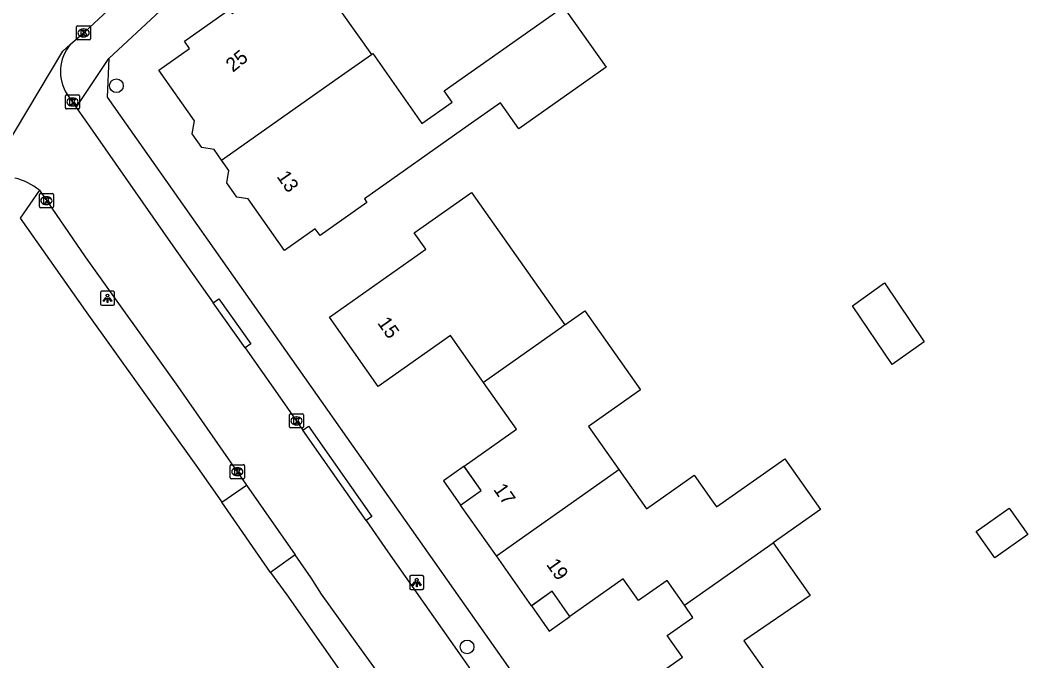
# Model space of a CAD drawing. Extents: x 161772 to 163123, y 383092 to 383917.
# Drawn here: x 162495.4 to 162567, y 383703.8 to 383749.3 of the extents above; entities that cross this region are included whole.
import ezdxf

# ---------------------------------------------------------------- set-up
doc = ezdxf.new("R2010")
doc.units = 0
for name, color, linetype in [('IMGEO_Boom', 7, 'Continuous'), ('IMGEO_Kolk', 7, 'Continuous'), ('IMGEO_Lichtpunt', 7, 'Continuous'), ('IMGEO_Pand', 7, 'Continuous'), ('IMGEO_Pand_nummerreeks', 7, 'Continuous'), ('IMGEO_Pand_overbouw', 7, 'Continuous'), ('IMGEO_Rijbaan_lokaal_open', 7, 'Continuous'), ('IMGEO_Voetpad_open', 7, 'Continuous')]:
    doc.layers.add(name, color=color, linetype=linetype)

msp = doc.modelspace()

# ---------------------------------------------------------------- linework, layer by layer
at = {"layer": 'IMGEO_Boom'}
for centre in [(162502.224, 383744.673), (162527.147, 383704.793)]:
    msp.add_circle(centre, 0.489, dxfattribs=at)
at = {"layer": 'IMGEO_Kolk'}
for p, q in [((162499.386, 383748.003), (162499.386, 383748.855)), ((162499.461, 383748.929), (162500.313, 383748.929)), ((162499.874, 383748.709), (162499.899, 383748.709)), ((162500.387, 383748.855), (162500.387, 383748.003)), ((162500.313, 383747.929), (162499.461, 383747.929)), ((162499.897, 383748.149), (162499.872, 383748.149)), ((162498.597, 383743.095), (162498.597, 383743.947)), ((162498.672, 383744.021), (162499.524, 383744.021)), ((162499.085, 383743.801), (162499.11, 383743.801)), ((162499.598, 383743.947), (162499.598, 383743.095)), ((162499.524, 383743.021), (162498.672, 383743.021)), ((162499.108, 383743.241), (162499.083, 383743.241)), ((162496.819, 383737.006), (162497.671, 383737.006)), ((162496.744, 383736.08), (162496.744, 383736.932)), ((162497.232, 383736.786), (162497.257, 383736.786)), ((162497.745, 383736.932), (162497.745, 383736.08)), ((162497.671, 383736.006), (162496.819, 383736.006)), ((162497.255, 383736.226), (162497.23, 383736.226)), ((162514.522, 383720.427), (162514.522, 383721.279)), ((162514.597, 383721.353), (162515.449, 383721.353)), ((162515.523, 383721.279), (162515.523, 383720.427)), ((162515.033, 383720.573), (162515.008, 383720.573)), ((162515.01, 383721.133), (162515.035, 383721.133)), ((162515.449, 383720.353), (162514.597, 383720.353)), ((162510.315, 383716.818), (162510.315, 383717.67)), ((162510.39, 383717.744), (162511.242, 383717.744)), ((162511.316, 383717.67), (162511.316, 383716.818)), ((162510.826, 383716.964), (162510.801, 383716.964)), ((162510.803, 383717.524), (162510.828, 383717.524)), ((162511.242, 383716.744), (162510.39, 383716.744))]:
    msp.add_line(p, q, dxfattribs=at)
for points in [[(162499.386, 383748.003), (162499.386, 383748.855)], [(162499.461, 383748.929), (162500.313, 383748.929)], [(162499.707, 383748.629), (162499.83, 383748.629), (162499.83, 383748.478), (162499.96, 383748.629), (162500.124, 383748.629), (162499.978, 383748.478), (162500.131, 383748.229), (162499.979, 383748.229), (162499.894, 383748.393), (162499.83, 383748.326), (162499.83, 383748.229), (162499.707, 383748.229), (162499.707, 383748.629)], [(162500.387, 383748.855), (162500.387, 383748.003)], [(162500.313, 383747.929), (162499.461, 383747.929)], [(162498.597, 383743.095), (162498.597, 383743.947)], [(162498.672, 383744.021), (162499.524, 383744.021)], [(162498.918, 383743.721), (162499.041, 383743.721), (162499.041, 383743.57), (162499.171, 383743.721), (162499.335, 383743.721), (162499.189, 383743.57), (162499.342, 383743.321), (162499.19, 383743.321), (162499.105, 383743.485), (162499.041, 383743.418), (162499.041, 383743.321), (162498.918, 383743.321), (162498.918, 383743.721)], [(162499.598, 383743.947), (162499.598, 383743.095)], [(162499.524, 383743.021), (162498.672, 383743.021)], [(162496.819, 383737.006), (162497.671, 383737.006)], [(162496.744, 383736.08), (162496.744, 383736.932)], [(162497.065, 383736.706), (162497.188, 383736.706), (162497.188, 383736.555), (162497.318, 383736.706), (162497.482, 383736.706), (162497.336, 383736.555), (162497.489, 383736.306), (162497.337, 383736.306), (162497.252, 383736.47), (162497.188, 383736.403), (162497.188, 383736.306), (162497.065, 383736.306), (162497.065, 383736.706)], [(162497.745, 383736.932), (162497.745, 383736.08)], [(162497.671, 383736.006), (162496.819, 383736.006)], [(162514.522, 383720.427), (162514.522, 383721.279)], [(162514.597, 383721.353), (162515.449, 383721.353)], [(162515.523, 383721.279), (162515.523, 383720.427)], [(162514.843, 383721.053), (162514.966, 383721.053), (162514.966, 383720.902), (162515.096, 383721.053), (162515.26, 383721.053), (162515.114, 383720.902), (162515.267, 383720.653), (162515.115, 383720.653), (162515.03, 383720.817), (162514.966, 383720.75), (162514.966, 383720.653), (162514.843, 383720.653), (162514.843, 383721.053)], [(162515.449, 383720.353), (162514.597, 383720.353)], [(162510.315, 383716.818), (162510.315, 383717.67)], [(162510.39, 383717.744), (162511.242, 383717.744)], [(162511.316, 383717.67), (162511.316, 383716.818)], [(162510.636, 383717.444), (162510.759, 383717.444), (162510.759, 383717.293), (162510.889, 383717.444), (162511.053, 383717.444), (162510.907, 383717.293), (162511.06, 383717.044), (162510.908, 383717.044), (162510.823, 383717.208), (162510.759, 383717.141), (162510.759, 383717.044), (162510.636, 383717.044), (162510.636, 383717.444)], [(162511.242, 383716.744), (162510.39, 383716.744)]]:
    msp.add_lwpolyline(points, dxfattribs=at)
for centre, start, end in [((162499.463, 383748.853), 91.55205, 178.44795), ((162499.463, 383748.853), 91.55205, 178.44795), ((162500.311, 383748.853), 1.55205, 88.44795), ((162500.311, 383748.853), 1.55205, 88.44795), ((162499.463, 383748.005), 181.55205, 268.44795), ((162499.463, 383748.005), 181.55205, 268.44795), ((162500.311, 383748.005), 271.55205, 358.44795), ((162500.311, 383748.005), 271.55205, 358.44795), ((162498.674, 383743.945), 91.55205, 178.44795), ((162498.674, 383743.945), 91.55205, 178.44795), ((162499.522, 383743.945), 1.55205, 88.44795), ((162499.522, 383743.945), 1.55205, 88.44795), ((162498.674, 383743.097), 181.55205, 268.44795), ((162498.674, 383743.097), 181.55205, 268.44795), ((162499.522, 383743.097), 271.55205, 358.44795), ((162499.522, 383743.097), 271.55205, 358.44795), ((162496.821, 383736.93), 91.55205, 178.44795), ((162496.821, 383736.93), 91.55205, 178.44795), ((162497.669, 383736.93), 1.55205, 88.44795), ((162497.669, 383736.93), 1.55205, 88.44795), ((162496.821, 383736.082), 181.55205, 268.44795), ((162496.821, 383736.082), 181.55205, 268.44795), ((162497.669, 383736.082), 271.55205, 358.44795), ((162497.669, 383736.082), 271.55205, 358.44795), ((162514.599, 383721.277), 91.55205, 178.44795), ((162514.599, 383721.277), 91.55205, 178.44795), ((162515.447, 383721.277), 1.55205, 88.44795), ((162515.447, 383721.277), 1.55205, 88.44795), ((162514.599, 383720.429), 181.55205, 268.44795), ((162514.599, 383720.429), 181.55205, 268.44795), ((162515.447, 383720.429), 271.55205, 358.44795), ((162515.447, 383720.429), 271.55205, 358.44795), ((162510.392, 383717.668), 91.55205, 178.44795), ((162510.392, 383717.668), 91.55205, 178.44795), ((162511.24, 383717.668), 1.55205, 88.44795), ((162511.24, 383717.668), 1.55205, 88.44795), ((162510.392, 383716.82), 181.55205, 268.44795), ((162510.392, 383716.82), 181.55205, 268.44795), ((162511.24, 383716.82), 271.55205, 358.44795), ((162511.24, 383716.82), 271.55205, 358.44795)]:
    msp.add_arc(centre, 0.0765, start, end, dxfattribs=at)
for centre, major_axis, ratio, start_param, end_param in [((162499.873, 383748.429), (-0.387, 0.002), 0.722429, 4.712389, 7.853982), ((162499.898, 383748.429), (-0.39, 0.002), 0.717154, 1.570796, 4.712389), ((162499.084, 383743.521), (-0.387, 0.002), 0.722429, 4.712389, 7.853982), ((162499.109, 383743.521), (-0.39, 0.002), 0.717154, 1.570796, 4.712389), ((162497.231, 383736.506), (-0.387, 0.002), 0.722429, 4.712389, 7.853982), ((162497.256, 383736.506), (-0.39, 0.002), 0.717154, 1.570796, 4.712389), ((162515.009, 383720.853), (-0.387, 0.002), 0.722429, 4.712389, 7.853982), ((162515.034, 383720.853), (-0.39, 0.002), 0.717154, 1.570796, 4.712389), ((162510.802, 383717.244), (-0.387, 0.002), 0.722429, 4.712389, 7.853982), ((162510.827, 383717.244), (-0.39, 0.002), 0.717154, 1.570796, 4.712389)]:
    msp.add_ellipse(centre, major_axis=major_axis, ratio=ratio, start_param=start_param, end_param=end_param, dxfattribs=at)
at = {"layer": 'IMGEO_Lichtpunt'}
for p, q in [((162501.087, 383729.97), (162501.087, 383729.163)), ((162501.087, 383729.97), (162501.087, 383729.163)), ((162501.989, 383730.065), (162501.181, 383730.065)), ((162501.989, 383730.065), (162501.181, 383730.065)), ((162502.083, 383729.163), (162502.083, 383729.97)), ((162502.083, 383729.163), (162502.083, 383729.97)), ((162501.181, 383729.069), (162501.989, 383729.069)), ((162501.181, 383729.069), (162501.989, 383729.069)), ((162523.067, 383709.77), (162523.067, 383708.963)), ((162523.067, 383709.77), (162523.067, 383708.963)), ((162523.969, 383709.865), (162523.161, 383709.865)), ((162523.969, 383709.865), (162523.161, 383709.865)), ((162524.063, 383708.963), (162524.063, 383709.77)), ((162524.063, 383708.963), (162524.063, 383709.77)), ((162523.161, 383708.869), (162523.969, 383708.869)), ((162523.161, 383708.869), (162523.969, 383708.869))]:
    msp.add_line(p, q, dxfattribs=at)
for points in [[(162501.461, 383729.634), (162501.5, 383729.606), (162501.312, 383729.344), (162501.274, 383729.371), (162501.461, 383729.634)], [(162501.563, 383729.586), (162501.61, 383729.586), (162501.61, 383729.264), (162501.563, 383729.264), (162501.563, 383729.586)], [(162501.673, 383729.606), (162501.711, 383729.633), (162501.898, 383729.371), (162501.859, 383729.343), (162501.673, 383729.606)], [(162523.441, 383709.434), (162523.48, 383709.406), (162523.292, 383709.144), (162523.254, 383709.171), (162523.441, 383709.434)], [(162523.543, 383709.386), (162523.59, 383709.386), (162523.59, 383709.064), (162523.543, 383709.064), (162523.543, 383709.386)], [(162523.653, 383709.406), (162523.691, 383709.433), (162523.878, 383709.171), (162523.839, 383709.143), (162523.653, 383709.406)]]:
    msp.add_lwpolyline(points, dxfattribs=at)
for centre in [(162501.586, 383729.768), (162523.566, 383709.568)]:
    msp.add_circle(centre, 0.0994, dxfattribs=at)
for centre, start, end in [((162501.181, 383729.97), 90, 180), ((162501.181, 383729.97), 90, 180), ((162501.989, 383729.97), 0, 90), ((162501.989, 383729.97), 0, 90), ((162501.181, 383729.163), 180, 270), ((162501.181, 383729.163), 180, 270), ((162501.989, 383729.163), 270, 0), ((162501.989, 383729.163), 270, 360), ((162523.161, 383709.77), 90, 180), ((162523.161, 383709.77), 90, 180), ((162523.969, 383709.77), 0, 90), ((162523.969, 383709.77), 0, 90), ((162523.161, 383708.963), 180, 270), ((162523.161, 383708.963), 180, 270), ((162523.969, 383708.963), 270, 0), ((162523.969, 383708.963), 270, 360)]:
    msp.add_arc(centre, 0.0946, start, end, dxfattribs=at)
at = {"layer": 'IMGEO_Pand'}
for points in [[(162509.7, 383739.39), (162509.176, 383740.133), (162508.302, 383740.284), (162507.609, 383741.266), (162507.767, 383742.176), (162505.229, 383745.776), (162507.428, 383747.326), (162507.059, 383747.849), (162510.109, 383750), (162510.266, 383750.111), (162510.333, 383750), (162510.455, 383749.798), (162510.744, 383750), (162517.086, 383754.432), (162518.497, 383752.412), (162517.12, 383751.435), (162520.343, 383746.892)], [(162520.343, 383746.892), (162520.438, 383746.959), (162523.942, 383741.989), (162526.083, 383743.498), (162525.519, 383744.299), (162533.605, 383750), (162534.002, 383750.28), (162534.2, 383750), (162537.028, 383745.989), (162530.816, 383741.61), (162529.514, 383743.457), (162527.228, 383741.846), (162519.845, 383736.641), (162520.033, 383736.374), (162516.696, 383734.022), (162516.356, 383734.504), (162514.164, 383732.958), (162511.577, 383736.627), (162510.79, 383736.763), (162510.074, 383737.779), (162510.224, 383738.646), (162509.7, 383739.39)], [(162509.7, 383739.39), (162517.977, 383745.224), (162520.343, 383746.892)], [(162528.322, 383723.595), (162525.973, 383726.925), (162520.834, 383723.302), (162517.362, 383728.227), (162524.212, 383733.056), (162523.391, 383734.22), (162527.466, 383737.093), (162534.106, 383727.674)], [(162557.363, 383724.867), (162554.539, 383729.041), (162556.826, 383730.657), (162559.649, 383726.482), (162557.363, 383724.867)], [(162534.106, 383727.674), (162535.514, 383728.666), (162539.47, 383723.055), (162535.772, 383720.448), (162537.926, 383717.392)], [(162534.106, 383727.674), (162533.863, 383727.502), (162528.322, 383723.595)], [(162529.228, 383711.258), (162526.685, 383714.865), (162528.152, 383715.899), (162526.94, 383717.617), (162526.933, 383717.627), (162530.671, 383720.263), (162528.322, 383723.595)], [(162537.926, 383717.392), (162539.897, 383714.596), (162543.29, 383716.988), (162544.512, 383715.255), (162544.876, 383714.739), (162549.736, 383718.166), (162552.279, 383714.561), (162548.906, 383712.188)], [(162529.228, 383711.258), (162537.362, 383716.993), (162537.926, 383717.392)], [(162565.686, 383714.646), (162567.009, 383712.77), (162564.67, 383711.121), (162563.347, 383712.997), (162565.686, 383714.646)], [(162542.597, 383707.751), (162548.906, 383712.188)], [(162548.906, 383712.188), (162551.547, 383708.443), (162546.832, 383705.214), (162550.118, 383700.553)], [(162542.597, 383707.751), (162541.36, 383709.506), (162539.342, 383708.083), (162538.25, 383709.631), (162534.458, 383706.957), (162533.196, 383708.746), (162531.744, 383707.723), (162531.728, 383707.712), (162529.228, 383711.258)], [(162541.426, 383694.423), (162538.777, 383698.18), (162540.026, 383699.06), (162538.494, 383701.233), (162538.471, 383701.266), (162542.453, 383704.074), (162541.376, 383705.603), (162543.203, 383706.89), (162542.597, 383707.751)]]:
    msp.add_lwpolyline(points, dxfattribs=at)
at = {"layer": 'IMGEO_Pand_overbouw'}
for points in [[(162526.933, 383717.627), (162525.466, 383716.593), (162526.685, 383714.865), (162528.152, 383715.899)], [(162533.196, 383708.746), (162531.728, 383707.712), (162532.99, 383705.922), (162534.458, 383706.957)]]:
    msp.add_lwpolyline(points, close=True, dxfattribs=at)
at = {"layer": 'IMGEO_Rijbaan_lokaal_open'}
for points in [[(162498.965, 383747.627), (162500, 383748.527), (162501.581, 383750), (162523.583, 383770.443)], [(162492.477, 383737.212), (162498.421, 383747.134), (162498.965, 383747.627)], [(162498.744, 383744.028), (162499.372, 383743.128)], [(162499.372, 383743.128), (162500, 383742.227), (162506.226, 383733.297), (162509.095, 383729.246)], [(162496.744, 383737.247), (162500, 383732.525), (162506.582, 383723.304), (162511.479, 383716.295)], [(162511.368, 383726.038), (162509.095, 383729.246)], [(162511.368, 383726.038), (162513.848, 383722.536), (162515.478, 383720.199)], [(162519.964, 383713.769), (162515.478, 383720.199)], [(162511.479, 383716.295), (162514.925, 383711.325)], [(162519.964, 383713.769), (162521.509, 383711.554), (162528.003, 383702.311)], [(162522.128, 383701.14), (162519.336, 383705.018), (162516.793, 383708.541), (162516.067, 383709.7), (162514.925, 383711.325)]]:
    msp.add_lwpolyline(points, dxfattribs=at)
for centre, radius, start, end in [((162501.206, 383745.683), 2.967, 139.06284, 213.90938), ((162494.024, 383733.956), 4.269, 50.42515, 76.81287)]:
    msp.add_arc(centre, radius, start, end, dxfattribs=at)
at = {"layer": 'IMGEO_Voetpad_open'}
for points in [[(162559.42, 383792.65), (162535.075, 383776.906), (162531.388, 383774.129), (162505.334, 383750), (162501.671, 383746.608)], [(162499.372, 383743.128), (162501.671, 383746.608)], [(162501.671, 383746.608), (162501.572, 383743.869), (162542.289, 383686.012), (162558.377, 383662.372), (162558.317, 383662.324), (162563.678, 383654.867), (162564.526, 383654.823)], [(162496.744, 383737.247), (162495.379, 383735.273)], [(162495.379, 383735.273), (162500, 383728.703), (162507.989, 383717.553), (162509.705, 383715.089)], [(162509.095, 383729.246), (162509.502, 383729.536), (162511.775, 383726.328), (162511.368, 383726.038)], [(162515.478, 383720.199), (162515.887, 383720.486), (162520.373, 383714.056), (162519.964, 383713.769)], [(162509.705, 383715.089), (162511.479, 383716.295)], [(162513.175, 383710.089), (162509.705, 383715.089)], [(162514.925, 383711.325), (162513.175, 383710.089)], [(162513.175, 383710.089), (162514.341, 383708.498), (162543.666, 383666.636)]]:
    msp.add_lwpolyline(points, dxfattribs=at)

# ---------------------------------------------------------------- texts
at = {"layer": 'IMGEO_Pand_nummerreeks'}
for s, rotation, p in [('25', 38.88092, (162510.501, 383745.592)), ('13', 304.76114, (162513.583, 383738.216)), ('15', 305.18286, (162520.734, 383727.817)), ('17', 305.18513, (162528.983, 383715.978)), ('19', 305.18513, (162532.745, 383710.643))]:
    msp.add_text(s, height=1, rotation=rotation, dxfattribs=at).set_placement(p)

doc.saveas('drawing.dxf')
